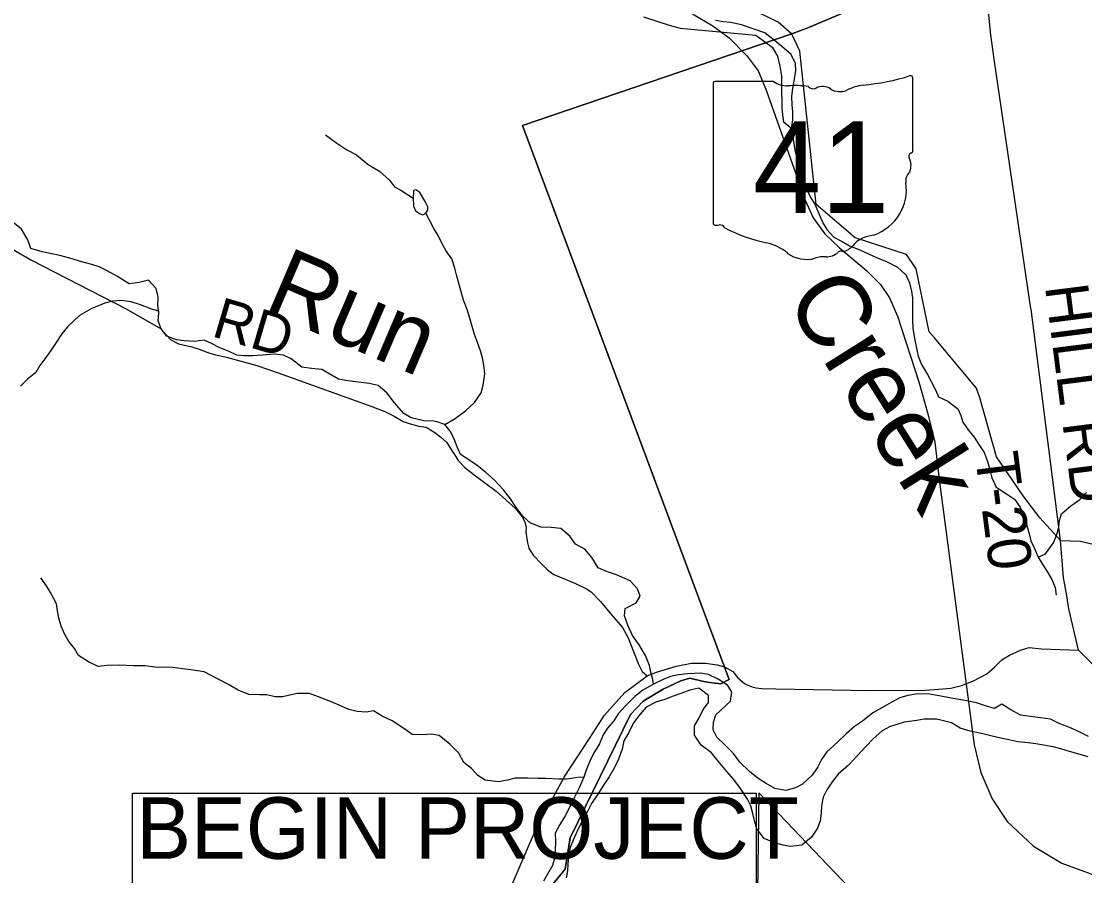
# Model space of a CAD drawing. Extents: x -139 to 835, y 0 to 440.
# Drawn here: x 414.36 to 462.76, y 305.95 to 344.84 of the extents above; entities that cross this region are included whole.
import ezdxf

# ---------------------------------------------------------------- set-up
doc = ezdxf.new("R2010")
doc.units = 0
for name, color, linetype in [('Default', 7, 'Continuous'), ('GM_X_County_Road', 7, 'Continuous'), ('GM_X_Major_River', 7, 'Continuous'), ('GM_X_Minor_Lake', 7, 'Continuous'), ('GM_X_Minor_River', 7, 'Continuous'), ('GM_X_Minor_River_Text', 7, 'Continuous'), ('GM_X_Rail_Line', 7, 'Continuous'), ('GM_X_State_Location', 7, 'Continuous'), ('GM_X_State_Route', 7, 'Continuous'), ('GM_X_State_Shield', 7, 'Continuous'), ('GM_X_Township_Road', 7, 'Continuous'), ('GM_X_Township_Road_Text', 7, 'Continuous'), ('SH_Text', 7, 'Continuous')]:
    doc.layers.add(name, color=color, linetype=linetype)

msp = doc.modelspace()

# ---------------------------------------------------------------- linework, layer by layer
at = {"layer": 'Default'}
for points in [[(438.412, 305.397), (439.118, 306.251), (439.343, 307.675), (442.08, 313.291), (442.658, 313.9), (443.573, 314.442), (444.379, 314.818), (444.78, 314.948), (445.353, 314.805), (445.677, 314.754), (446.19, 314.682), (446.58, 314.883), (446.356, 315.484), (437.173, 340.096), (449.424, 344.271), (450.155, 344.542), (458.032, 347.876)], [(458.032, 347.876), (450.155, 344.542), (449.424, 344.271), (437.173, 340.096), (446.356, 315.484), (446.58, 314.883), (446.19, 314.682), (445.677, 314.754), (445.353, 314.805), (444.78, 314.948), (444.379, 314.818), (443.573, 314.442), (442.658, 313.9), (442.08, 313.291), (439.343, 307.675), (439.118, 306.251), (438.412, 305.397)]]:
    msp.add_lwpolyline(points, dxfattribs=at)
at = {"layer": 'GM_X_County_Road'}
for points in [[(459.13, 315.869), (459.34, 315.998), (459.83, 316.227), (460.225, 316.338), (460.785, 316.277), (462.469, 316.225)], [(442.839, 315.057), (443.266, 315.214), (444.158, 315.496), (444.857, 315.626), (445.505, 315.631), (446.034, 315.553), (446.363, 315.467), (446.739, 315.25), (446.978, 314.958)], [(446.978, 314.958), (447.276, 314.708), (447.56, 314.562), (447.811, 314.499), (448.061, 314.468), (448.697, 314.457), (452.984, 314.39), (455.493, 314.405), (456.108, 314.439), (456.671, 314.486), (457.145, 314.607), (457.7, 314.823), (458.31, 315.145), (458.645, 315.449), (458.981, 315.778), (459.13, 315.869)], [(411.116, 294.343), (416.995, 293.57), (417.691, 293.503), (418.565, 293.58), (420.5, 294.295), (421.856, 294.869), (427.525, 298.381), (428.221, 299.019), (428.673, 300.232), (429.043, 300.462), (429.487, 300.755), (431.27, 301.478), (432.683, 302.353), (434.337, 303.312), (435.703, 304.048), (436.18, 304.394), (436.542, 305.181), (437.762, 308.033), (439.074, 310.435), (440.22, 312.201), (440.91, 313.258), (441.831, 314.29), (442.373, 314.697), (442.839, 315.057)]]:
    msp.add_lwpolyline(points, dxfattribs=at)
at = {"layer": 'GM_X_Major_River'}
for points in [[(461.204, 313.083), (459.835, 313.266), (459.395, 313.499), (458.98, 313.756), (458.651, 313.567), (458.248, 313.692), (457.832, 313.816), (457.468, 313.904), (457.116, 313.956), (456.673, 314.033), (456.139, 314.147), (455.696, 314.224), (455.161, 314.23), (454.703, 314.163), (454.336, 314.047), (453.955, 313.835), (453.52, 313.6), (453.112, 313.364), (452.65, 312.985), (452.281, 312.749), (451.898, 312.418), (451.501, 312.038), (451.025, 311.587), (450.785, 311.242), (450.611, 310.908), (450.357, 310.527), (449.921, 310.123), (449.592, 309.947), (449.159, 309.832), (448.652, 309.921), (448.263, 310.154), (447.901, 310.386), (447.5, 310.69), (447.062, 311.127), (446.767, 311.514), (446.381, 311.915), (446.02, 312.267), (445.842, 312.593), (445.86, 312.941), (445.969, 313.275), (446.63, 313.892), (446.701, 314.311), (446.523, 314.613), (446.083, 314.894), (445.642, 315.115), (445.29, 315.179), (444.702, 315.15), (444.258, 315.095), (443.904, 315.015), (443.576, 314.886), (443.129, 314.675), (442.642, 314.405), (442.286, 314.109), (441.876, 313.705), (441.531, 313.325), (441.331, 313.003), (441.039, 312.67), (440.839, 312.361), (440.676, 311.954), (440.396, 311.514), (440.248, 311.191), (440.086, 310.809), (439.964, 310.438), (439.748, 309.949), (439.533, 309.531), (439.372, 309.173), (439.117, 308.684), (438.864, 308.291), (438.662, 307.885), (438.67, 307.489), (438.664, 307.093), (438.634, 306.757), (438.538, 306.422), (438.31, 306.017), (438.123, 305.707)], [(448.163, 307.647), (447.83, 308.094), (447.743, 308.407), (447.657, 308.78), (447.57, 309.141), (447.418, 309.443), (447.098, 309.927), (446.79, 310.338), (446.469, 310.702), (446.096, 311.15), (445.776, 311.549), (445.31, 311.903), (445.003, 312.35), (444.996, 312.77), (445.197, 313.116), (445.398, 313.522), (445.637, 313.843), (445.629, 314.155), (445.202, 314.484), (444.783, 314.393), (444.377, 314.253), (443.983, 314.114), (443.655, 313.973), (443.235, 313.846), (442.801, 313.623), (442.523, 313.314), (442.217, 312.909), (441.989, 312.444), (441.788, 312.098), (441.704, 311.715), (441.542, 311.261), (441.34, 310.843), (441.113, 310.462), (440.886, 310.128), (440.566, 309.616), (440.313, 309.246), (440.138, 308.9), (439.871, 308.423), (439.656, 307.982), (439.48, 307.576), (439.345, 307.241), (439.262, 306.894), (439.23, 306.475), (439.213, 306.175), (439.157, 305.863)], [(462.917, 311.372), (462.553, 311.472), (462.058, 311.61), (461.668, 311.722), (461.317, 311.822), (460.874, 311.899), (460.535, 311.95), (460.184, 312.002), (459.714, 312.055), (459.311, 312.132), (458.946, 312.208), (458.543, 312.308), (458.113, 312.409), (457.54, 312.535), (457.085, 312.672), (456.697, 312.917), (456.033, 313.08), (455.446, 313.075), (455.118, 313.018), (454.543, 312.94), (453.874, 312.732), (453.545, 312.543), (453.122, 312.176), (452.804, 311.844), (452.406, 311.404), (452.009, 310.988), (451.533, 310.574), (451.267, 310.228), (451.014, 309.859), (450.853, 309.525), (450.782, 309.142), (450.764, 308.794), (450.72, 308.446), (450.598, 308.124), (450.331, 307.707), (449.883, 307.352), (449.372, 307.285), (449.034, 307.349), (448.643, 307.449), (448.163, 307.647)], [(462.93, 312.284), (462.411, 312.542), (461.957, 312.739), (461.619, 312.874), (461.204, 313.083)]]:
    msp.add_lwpolyline(points, dxfattribs=at)
at = {"layer": 'GM_X_Minor_Lake'}
for points in [[(432.773, 336.105), (432.866, 336.248), (432.869, 336.404), (432.741, 336.646), (432.499, 337.056), (432.318, 337.167), (432.213, 337.144), (432.195, 336.796), (432.216, 336.436), (432.305, 336.219), (432.512, 336.072), (432.641, 336.033)], [(432.641, 336.033), (432.773, 336.105)]]:
    msp.add_lwpolyline(points, dxfattribs=at)
at = {"layer": 'GM_X_Minor_River'}
for points in [[(442.679, 345.038), (443.851, 344.67), (444.346, 344.534), (447.795, 344.206)], [(448.201, 344.31), (447.144, 344.682), (446.648, 344.782), (446.309, 344.82), (445.956, 344.871)], [(447.795, 344.206), (448.131, 343.974), (448.531, 343.658), (448.774, 343.259), (448.885, 342.802), (448.957, 342.345), (448.953, 342.045), (448.959, 341.589), (448.968, 341.241), (448.976, 340.905), (449.011, 340.58), (449.046, 340.268), (449.407, 339.976)], [(449.407, 339.976), (449.478, 340.359), (449.47, 340.719), (449.448, 341.043), (449.427, 341.416), (449.472, 341.799), (449.528, 342.123), (449.613, 342.602), (449.592, 342.914), (449.402, 343.336), (449.066, 343.616), (448.627, 343.981), (448.201, 344.31)], [(449.407, 339.976), (449.563, 338.978), (449.65, 338.653), (449.775, 338.292), (449.963, 337.701), (450.088, 337.256), (450.277, 336.822), (450.469, 336.52), (450.659, 336.098), (450.836, 335.676), (451.028, 335.373), (451.336, 335.01), (451.712, 334.814), (452.049, 334.618), (452.529, 334.433), (452.944, 334.236), (453.386, 334.039), (453.736, 333.915), (454.242, 333.658), (454.616, 333.306), (454.78, 332.932), (454.867, 332.559), (454.915, 332.258), (454.924, 331.946), (454.919, 331.622), (454.927, 331.262), (454.935, 330.854), (455.032, 330.325), (455.178, 329.603), (455.33, 329.217), (455.598, 328.77), (455.776, 328.444), (455.967, 328.07), (456.106, 327.745), (456.521, 327.56), (456.986, 327.207), (457.126, 326.893), (457.213, 326.592), (457.456, 326.254), (457.726, 325.915), (457.943, 325.576), (458.186, 325.213), (458.325, 324.852), (458.424, 324.491), (458.536, 324.057), (458.726, 323.635), (459.204, 323.33), (459.554, 323.086), (459.823, 322.735), (459.949, 322.434), (460.113, 321.952), (460.212, 321.579), (460.298, 321.194), (460.476, 320.844), (460.64, 320.446), (460.844, 320.108), (461.049, 319.793), (461.266, 319.443), (461.405, 319.069), (461.452, 318.721)], [(428.202, 339.674), (428.719, 339.296), (429.172, 338.991), (429.612, 338.758), (430.141, 338.319), (430.659, 338.026), (431.123, 337.612), (431.341, 337.31), (431.632, 337.158), (432.195, 336.796)], [(433.632, 326.483), (434.106, 326.765), (434.581, 327.12), (434.991, 327.499), (435.284, 327.928), (435.38, 328.287), (435.452, 328.802), (435.405, 329.187), (435.358, 329.523), (435.258, 329.849), (435.12, 330.222), (434.994, 330.584), (434.882, 330.945), (434.769, 331.33), (434.657, 331.728), (434.494, 332.149), (434.369, 332.583), (434.257, 332.968), (434.17, 333.305), (434.096, 333.606), (433.958, 334.028), (433.676, 334.403), (433.498, 334.741), (433.333, 335.091), (433.129, 335.441), (432.773, 336.105)], [(443.129, 314.675), (443.106, 314.891), (443.019, 315.216), (442.958, 315.529), (442.769, 315.975), (442.475, 316.459), (442.181, 316.882), (441.965, 317.364), (441.814, 317.786), (441.845, 318.122), (442.345, 318.368), (442.532, 318.678), (442.406, 319.004), (442.071, 319.379), (441.449, 319.65), (441.046, 319.787), (440.617, 319.972), (440.323, 320.431), (440.003, 320.819), (439.588, 321.051), (439.332, 321.402), (438.919, 321.755), (438.475, 321.796), (438.006, 321.813), (437.526, 322.022), (437.19, 322.326), (436.882, 322.714), (436.627, 323.101), (436.306, 323.524), (435.907, 323.937), (435.495, 324.314), (435.107, 324.618), (434.771, 324.85), (434.357, 325.13), (434.206, 325.48), (434.041, 325.866), (433.876, 326.18), (433.632, 326.483), (433.281, 326.607), (433.138, 326.644), (432.682, 326.662), (432.109, 326.788), (431.773, 326.996), (431.349, 327.481), (431.002, 327.929), (430.602, 328.269), (430.199, 328.358), (429.704, 328.424), (429.222, 328.477), (428.792, 328.554), (428.041, 328.995), (427.572, 329.036), (427.129, 329.101), (426.639, 329.479), (426.289, 329.639), (425.885, 329.692), (425.336, 329.65), (424.905, 329.619), (424.527, 329.612), (424.175, 329.64), (423.825, 329.812), (423.371, 329.997), (423.021, 330.182), (422.684, 330.33), (422.227, 330.275), (421.77, 330.292), (421.419, 330.345), (420.99, 330.506), (420.734, 330.845), (420.596, 331.207), (420.627, 331.554), (420.579, 331.903), (420.585, 332.299), (420.499, 332.684), (420.152, 333.06), (419.733, 332.957), (419.276, 332.89), (418.745, 333.221), (418.266, 333.491), (417.904, 333.663), (417.566, 333.775), (417.059, 333.914), (416.683, 334.038), (416.111, 334.189), (415.682, 334.278), (415.318, 334.355), (414.799, 334.505), (414.661, 334.891), (414.367, 335.375), (413.903, 335.765)], [(420.627, 331.554), (420.615, 331.65), (420.251, 331.751), (419.784, 331.936), (419.369, 332.073), (418.913, 332.139), (418.521, 332.108), (418.168, 332.016), (417.538, 331.759), (417.012, 331.454), (416.484, 330.944), (416.205, 330.612), (415.926, 330.183), (415.713, 329.862), (415.433, 329.481), (415.208, 329.172), (415.021, 328.862), (414.651, 328.555), (414.334, 328.235)], [(460.64, 320.446), (460.969, 320.61), (461.341, 321.11), (461.477, 321.445), (461.573, 321.816), (461.603, 322.116), (461.699, 322.427), (462.122, 322.794), (462.531, 323.077), (462.836, 323.398)], [(439.964, 310.438), (439.689, 310.417), (439.179, 310.351), (438.827, 310.355), (438.227, 310.374), (437.874, 310.378), (437.417, 310.395), (436.843, 310.39), (436.489, 310.298), (436.071, 310.23), (435.471, 310.309), (435.135, 310.517), (434.852, 310.832), (434.503, 311.112), (434.274, 311.535), (433.862, 311.947), (433.372, 312.337), (433.033, 312.401), (432.602, 312.37), (432.158, 312.387), (431.822, 312.619), (431.24, 312.997), (430.786, 313.219), (430.385, 313.451), (430.058, 313.395), (429.654, 313.424), (429.264, 313.524), (428.836, 313.721), (428.433, 313.882), (427.849, 314.105), (427.473, 314.241), (426.938, 314.247), (426.584, 314.167), (426.257, 314.099), (425.918, 314.091), (425.541, 314.191), (425.201, 314.184), (424.719, 314.201), (424.239, 314.399), (423.825, 314.644), (423.294, 314.914), (422.685, 315.233), (422.073, 315.324), (421.721, 315.365), (421.266, 315.43), (420.901, 315.446), (420.574, 315.438), (419.988, 315.505), (419.466, 315.5), (418.815, 315.544), (418.267, 315.526), (417.862, 315.471), (417.421, 315.693), (416.969, 315.974), (416.778, 316.288), (416.534, 316.615), (416.343, 316.93), (416.179, 317.316), (416.092, 317.617), (416.031, 317.918), (415.958, 318.326), (415.691, 318.846), (415.513, 319.148), (415.257, 319.511)]]:
    msp.add_lwpolyline(points, dxfattribs=at)
at = {"layer": 'GM_X_Rail_Line'}
msp.add_lwpolyline([(444.906, 345.179), (445.837, 344.639), (446.578, 344.096), (447.394, 343.252), (447.895, 342.593), (448.243, 341.756), (450.037, 336.701), (450.401, 335.9), (450.925, 335.166), (451.594, 334.538), (452.83, 333.496), (453.456, 332.868), (453.878, 332.254), (454.242, 331.426), (455.202, 328.434), (455.624, 326.978), (455.929, 325.683), (456.133, 323.987), (457.719, 311.914), (458.024, 310.645), (458.548, 309.456), (459.232, 308.415), (460.425, 307.293), (461.72, 306.518), (463.204, 305.984)], dxfattribs=at)
at = {"layer": 'GM_X_State_Route'}
for points in [[(461.936, 318.695), (461.787, 319.53), (461.653, 321.204), (460.72, 322.248), (459.959, 323.239), (459.079, 324.531), (458.741, 325.026), (457.98, 327.702), (457.828, 328.148), (457.128, 328.986), (455.915, 330.436), (455.682, 330.714), (455.08, 333.568), (454.648, 334.227), (452.306, 334.994), (450.539, 336.505), (449.794, 343.483), (449.431, 344.255), (448.803, 344.8), (447.829, 345.277), (446.736, 345.459)], [(470.418, 307.606), (470.395, 307.727), (470.323, 308.109), (470.008, 309.755), (469.895, 310.275), (469.623, 310.919), (469.294, 311.543), (468.841, 312.084), (468.399, 312.489), (467.833, 312.895), (467.402, 313.155), (465.045, 314.194), (464.422, 314.496), (463.798, 314.891), (462.469, 316.225), (462.04, 318.107), (461.936, 318.695)]]:
    msp.add_lwpolyline(points, dxfattribs=at)
at = {"layer": 'GM_X_State_Shield'}
for p, q in [((454.931, 338.953), (454.931, 342.263)), ((445.844, 341.997), (445.844, 335.67)), ((448.595, 342.106), (445.933, 342.106)), ((454.93, 338.954), (454.931, 338.953))]:
    msp.add_line(p, q, dxfattribs=at)
for centre, major_axis, start_param, end_param in [((451.694, 350.733), (9.637, 0), 4.814394, 5.042369), ((454.83, 342.277), (0.101, 0), 6.141152, 7.989035), ((445.948, 342.011), (0.105, 0), 1.712693, 3.28349), ((449.228, 342.841), (1.021, 0), 4.042523, 4.731795), ((449.567, 338.554), (3.666, 0), 1.404758, 1.657858), ((450.399, 342.043), (0.295, 0), 3.836095, 5.185415), ((450.831, 341.312), (0.612, 0), 0.950623, 2.079405), ((451.622, 342.315), (0.737, 0), 4.081561, 5.145723), ((452.923, 340.173), (1.939, 0), 1.699011, 2.107814), ((454.908, 338.71), (0.157, 0), 1.883978, 3.671073), ((454.823, 338.94), (0.108, 0), 5.05454, 6.418171), ((453.912, 338.291), (0.94, 0), 5.934695, 6.695948), ((455.293, 337.568), (0.684, 0), 2.387724, 3.262537), ((452.234, 337.147), (2.41, 0), 5.101752, 6.440018), ((445.949, 335.656), (0.106, 0), 3.00124, 4.508301), ((445.965, 336.303), (0.81, 0), 4.665946, 4.897461), ((446.131, 335.305), (0.292, 0), 0.519207, 1.627899), ((449.821, 340.99), (6.959, 0), 4.195997, 4.488961), ((453.25, 333.893), (1.32, 0), 1.647645, 2.488434), ((447.746, 332.827), (2.177, 0), 0.823519, 1.323587), ((451.578, 335.056), (0.779, 0), 4.937069, 5.64225), ((450.101, 335.273), (1.382, 0), 4.026481, 4.996735), ((450.899, 333.086), (1.135, 0), 1.495662, 1.94098), ((451, 334.799), (0.736, 0), 4.691044, 5.507374), ((451.666, 334.187), (0.207, 0), 1.147584, 2.315152)]:
    msp.add_ellipse(centre, major_axis=major_axis, ratio=0.917426, start_param=start_param, end_param=end_param, dxfattribs=at)
at = {"layer": 'GM_X_Township_Road'}
msp.add_line((461.653, 321.204), (460.315, 331.733), dxfattribs=at)
for points in [[(458.49, 344.221), (458.286, 346.201)], [(458.669, 342.906), (458.524, 343.891), (458.49, 344.221)], [(460.315, 331.733), (460.31, 331.766), (458.669, 342.906)], [(412.415, 335.362), (414.797, 333.987), (419.138, 331.757), (420.696, 330.861), (421.159, 330.365), (421.514, 330.163), (422.128, 330.022), (422.463, 329.918), (422.85, 329.77), (423.145, 329.678), (423.706, 329.562), (425.089, 329.169), (426.049, 328.841)], [(426.049, 328.841), (426.433, 328.709), (430.147, 327.373), (430.909, 327.077), (431.335, 326.872), (431.74, 326.627), (432.017, 326.53), (432.453, 326.422), (432.783, 326.364), (433.187, 326.129), (433.454, 325.914), (433.709, 325.68), (433.965, 325.279), (434.082, 325.123), (434.242, 324.849), (434.54, 324.527), (434.976, 324.195), (435.977, 323.452), (436.85, 322.671), (437.159, 322.29), (437.275, 322.064), (437.341, 321.807), (437.319, 321.585), (437.406, 321.1), (437.457, 320.867), (437.659, 320.548), (438.036, 320.155), (438.326, 319.863), (438.601, 319.663), (438.935, 319.524), (439.587, 319.251), (440.109, 318.998), (440.311, 318.857), (440.716, 318.431), (441.222, 317.827), (441.72, 317.246), (441.975, 316.774), (442.22, 316.153), (442.453, 315.589), (442.624, 315.245), (442.839, 315.057)], [(461.653, 321.204), (462.568, 321.181), (463.204, 321.035)]]:
    msp.add_lwpolyline(points, dxfattribs=at)
at = {"layer": 'SH_Text'}
for points in [[(447.801, 297.383), (419.429, 297.383), (419.429, 309.718), (447.801, 309.718)], [(464.221, 292.642), (447.929, 309.729), (447.761, 297.325)]]:
    msp.add_lwpolyline(points, close=True, dxfattribs=at)

# ---------------------------------------------------------------- texts
at = {"layer": 'GM_X_Minor_River_Text'}
for s, height, rotation, p in [('Run', 3.1591, 336.7986, (425.3, 331.706)), ('Creek', 3.3063, 302.176, (449.075, 332.204))]:
    msp.add_text(s, height=height, rotation=rotation, dxfattribs=at).set_placement(p)
at = {"layer": 'GM_X_State_Location'}
for s in ['s', 'r']:
    msp.add_text(s, height=0.00599, dxfattribs=at).set_placement((450.285, 338.413))
msp.add_text('41', height=0.00599, rotation=0, dxfattribs=at).set_placement((448.641, 337.977))
at = {"layer": 'GM_X_State_Shield'}
msp.add_text('41', height=4.1684, dxfattribs=at).set_placement((447.661, 336.116))
at = {"layer": 'GM_X_Township_Road_Text'}
for s, height, rotation, p in [('HILL RD', 1.9603, 277.2849, (460.944, 332.782)), ('RD', 1.8549, 343.5697, (422.967, 330.527)), ('T-20', 1.9603, 277.3289, (457.759, 325.113))]:
    msp.add_text(s, height=height, rotation=rotation, dxfattribs=at).set_placement(p)
at = {"layer": 'SH_Text'}
msp.add_text('BEGIN PROJECT', height=2.79999, dxfattribs=at).set_placement((419.59, 306.724))

doc.saveas('drawing.dxf')
